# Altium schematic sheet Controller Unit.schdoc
size 495 x 282 mm
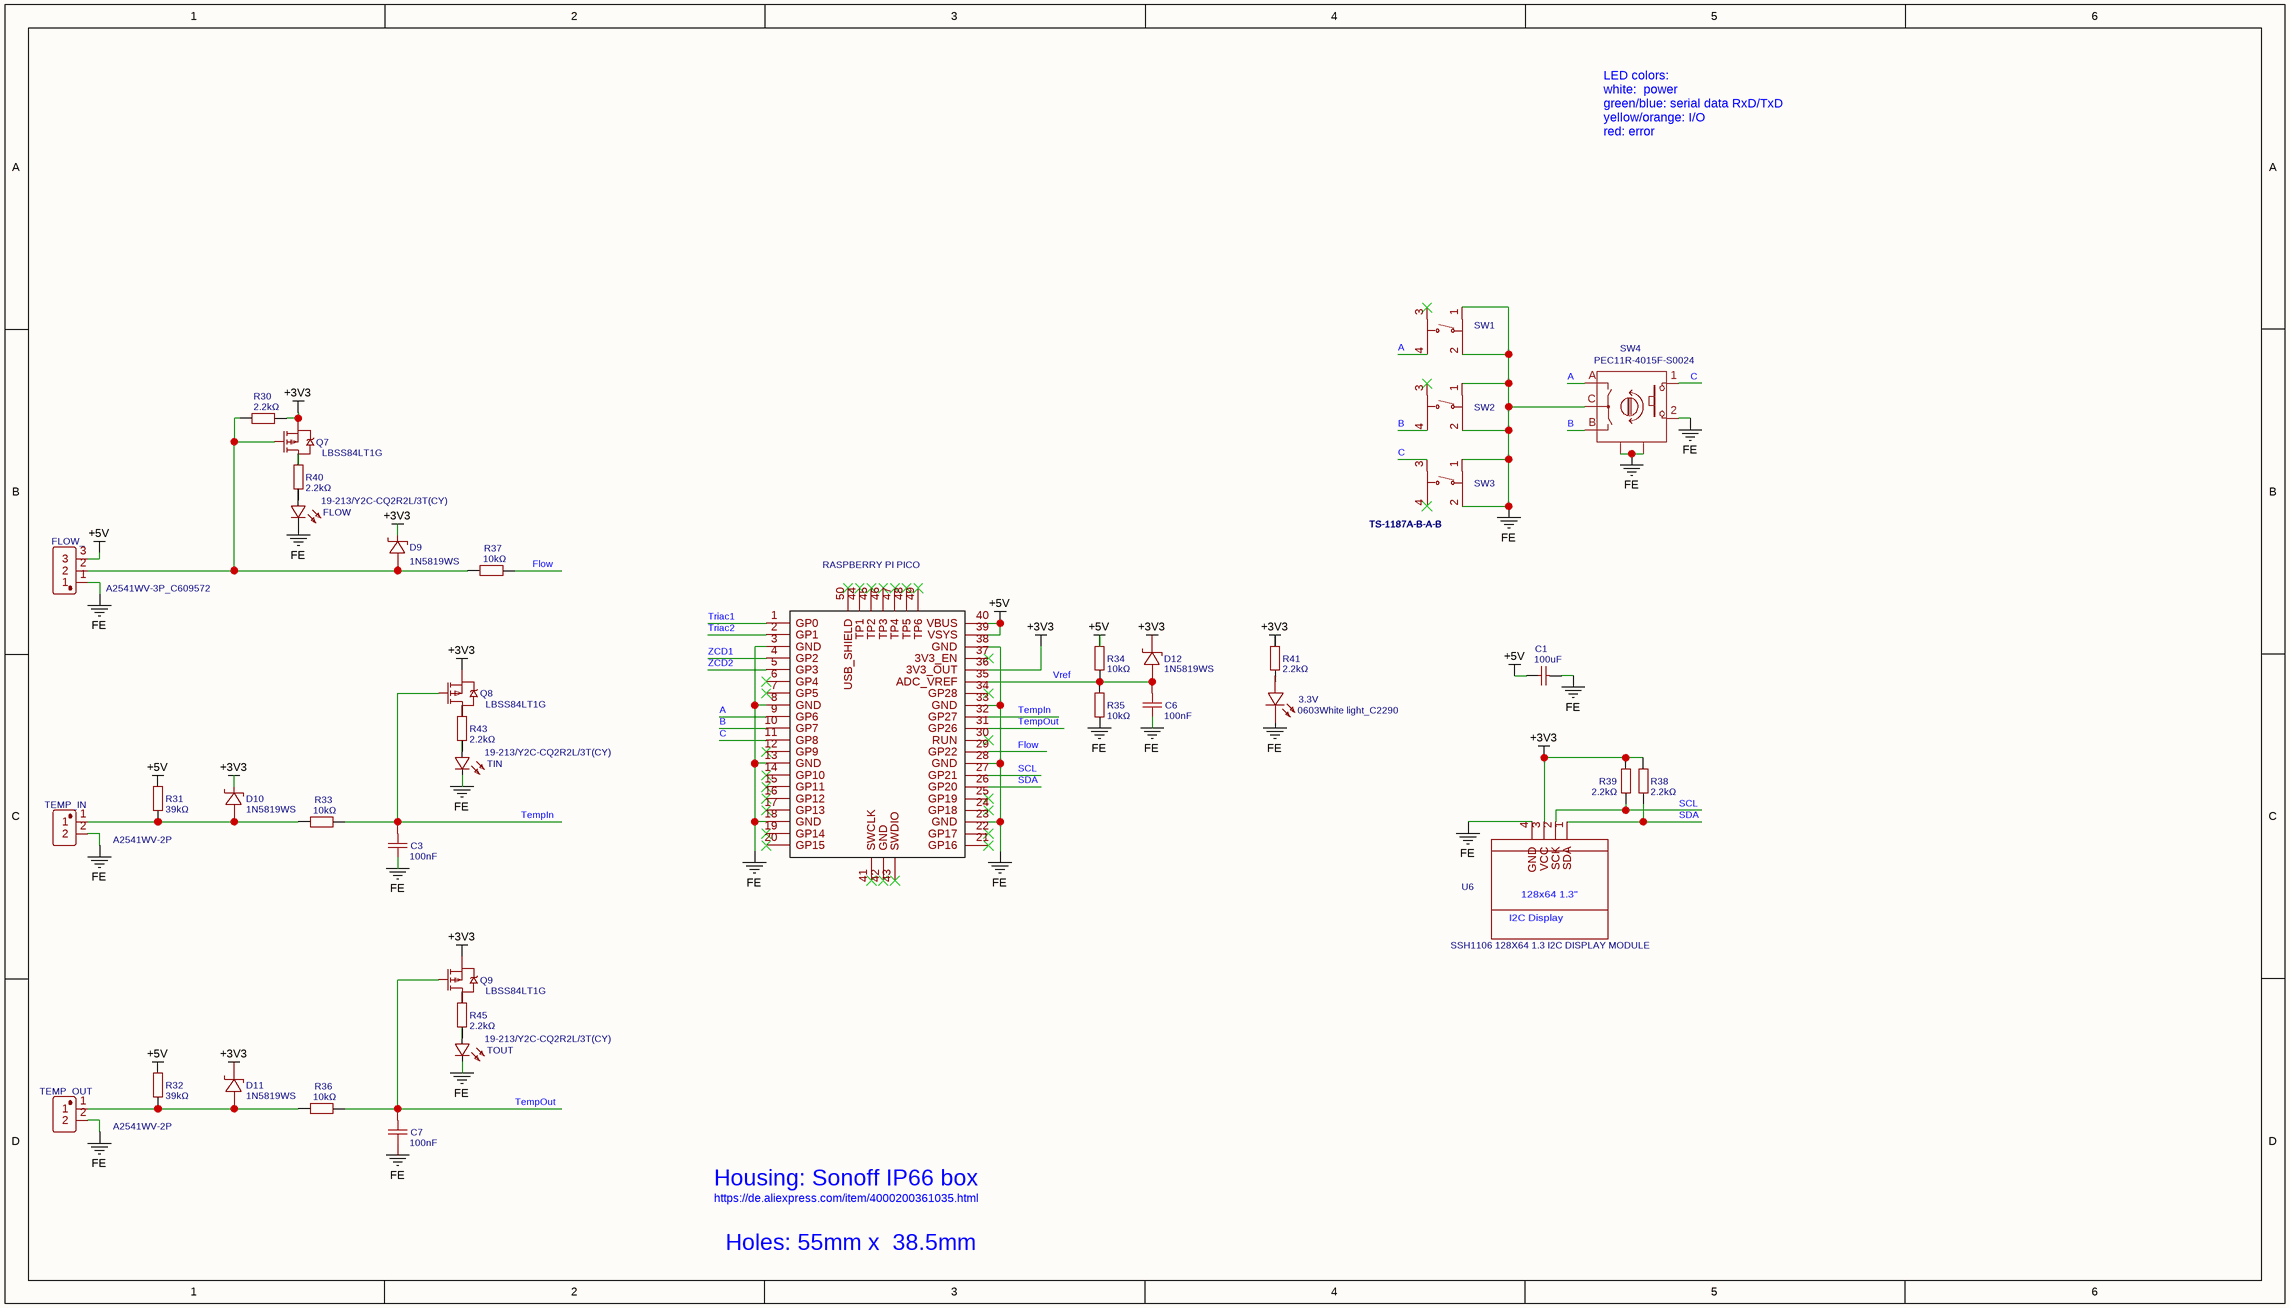
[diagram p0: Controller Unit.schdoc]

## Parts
3.3V  0603White light_C2290  [LED0603-R-RD_WHITE]
C1  100uF  [C1206]
C3  100nF  [C0603]
C6  100nF  [C0603]
C7  100nF  [C0603]
D9  1N5819WS  [SOD-323_L1.8-W1.3-LS2.5-RD]
D10  1N5819WS  [SOD-323_L1.8-W1.3-LS2.5-RD]
D11  1N5819WS  [SOD-323_L1.8-W1.3-LS2.5-RD]
D12  1N5819WS  [SOD-323_L1.8-W1.3-LS2.5-RD]
FLOW  19-213/Y2C-CQ2R2L/3T(CY)  [LED0603-R-RD]
FLOW_  A2541WV-3P_C609572  [HDR-TH_3P-P2.54-V-M]
GP1  RASPBERRY PI PICO  [RASPBERRY PI PICO]
Q7  LBSS84LT1G  [SOT-23_L2.9-W1.3-P1.90-LS2.4-BR]
Q8  LBSS84LT1G  [SOT-23_L2.9-W1.3-P1.90-LS2.4-BR]
Q9  LBSS84LT1G  [SOT-23_L2.9-W1.3-P1.90-LS2.4-BR]
R30  2.2kΩ  [R0603]
R31  39kΩ  [R0603]
R32  39kΩ  [R0603]
R33  10kΩ  [R0603]
R34  10kΩ  [R0603]
R35  10kΩ  [R0603]
R36  10kΩ  [R0603]
R37  10kΩ  [R0603]
R38  2.2kΩ  [R0603]
R39  2.2kΩ  [R0603]
R40  2.2kΩ  [R0603]
R41  2.2kΩ  [R0603]
R43  2.2kΩ  [R0603]
R45  2.2kΩ  [R0603]
SW1  TS-1187A-B-A-B  [SW-SMD_4P-L5.1-W5.1-P3.70-LS6.5-TL-2]
SW2  TS-1187A-B-A-B  [SW-SMD_4P-L5.1-W5.1-P3.70-LS6.5-TL-2]
SW3  TS-1187A-B-A-B  [SW-SMD_4P-L5.1-W5.1-P3.70-LS6.5-TL-2]
SW4  PEC11R-4015F-S0024  [SW-TH_PEC11R-4XXXF-SXXXX]
TEMP_IN  A2541WV-2P  [HDR-TH_P2.54-H-M_A2541WV-2P]
TEMP_OUT  A2541WV-2P  [HDR-TH_P2.54-H-M_A2541WV-2P]
TIN  19-213/Y2C-CQ2R2L/3T(CY)  [LED0603-R-RD]
TOUT  19-213/Y2C-CQ2R2L/3T(CY)  [LED0603-R-RD]
U6  SSH1106 128X64 1.3 I2C DISPLAY MODULE  [SSH1106 128X64 1.3 I2C OLED DISPLAY MODULE]

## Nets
+3V3: D9.1(C) D10.1(C) D11.1(C) D12.1(C) GP1.36(3V3_OUT) Q7.2(S) Q8.2(S) Q9.2(S) R30.1 R38.2 R39.2 R41.2 U6.3(VCC)
+5V: C1.2 FLOW_.3 GP1.39(VSYS) GP1.40(VBUS) R31.2 R32.1 R34.2
FE: 3.3V.2(K) C1.1 C3.1 C6.1 C7.1 FLOW.2(C) FLOW_.1 GP1.3(GND) GP1.8(GND) GP1.13(GND) GP1.18(GND) GP1.23(GND) GP1.28(GND) GP1.33(GND) GP1.38(GND) R35.1 SW1.1(A) SW1.2(B) SW2.1(A) SW2.2(B) SW3.1(A) SW3.2(B) SW4.2 SW4.C SW4.MT1 SW4.MT2 TEMP_IN.2 TEMP_OUT.2 TIN.2(C) TOUT.2(C) U6.4(GND)
A: GP1.9(GP6) SW1.4(D) SW4.A
B: GP1.10(GP7) SW2.4(D) SW4.B
C: GP1.11(GP8) SW3.3(C) SW4.1
Flow: GP1.29(GP22) R37.2
SCL: GP1.27(GP21) R39.1 U6.2(SCK)
SDA: GP1.26(GP20) R38.1 U6.1(SDA)
TempIn: C3.2 GP1.32(GP27) Q8.1(G) R33.2
TempOut: C7.2 GP1.31(GP26) Q9.1(G) R36.2
Triac1: GP1.1(GP0)
Triac2: GP1.2(GP1)
Vref: C6.2 D12.2(A) GP1.35(ADC_VREF) R34.1 R35.2
ZCD1: GP1.4(GP2)
ZCD2: GP1.5(GP3)
Net3.3V_1: 3.3V.1(A) R41.1
NetD9_2: D9.2(A) FLOW_.2 Q7.1(G) R30.2 R37.1
NetD10_2: D10.2(A) R31.1 R33.1 TEMP_IN.1
NetD11_2: D11.2(A) R32.2 R36.1 TEMP_OUT.1
NetFLOW_1: FLOW.1(A) R40.1
NetQ7_3: Q7.3(D) R40.2
NetQ8_3: Q8.3(D) R43.2
NetQ9_3: Q9.3(D) R45.2
NetR43_1: R43.1 TIN.1(A)
NetR45_1: R45.1 TOUT.1(A)

Not connected (* = marked no-connect by the designer): GP1 6(GP4)* 7(GP5)* 12(GP9)* 14(GP10)* 15(GP11)* 16(GP12)* 17(GP13)* 19(GP14)* 20(GP15)* 21(GP16)* 22(GP17)* 24(GP18)* 25(GP19)* 30(RUN)* 34(GP28)* 37(3V3_EN)* 41(SWCLK)* 42(GND)* 43(SWDIO)* 44(TP1)* 45(TP2)* 46(TP3)* 47(TP4)* 48(TP5)* 49(TP6)* 50(USB_SHIELD)*; SW1 3(C)*; SW2 3(C)*; SW3 4(D)*

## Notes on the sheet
- LED colors:
  white:  power
  green/blue: serial data RxD/TxD
  yellow/orange: I/O
  red: error
- https://de.aliexpress.com/item/4000200361035.html
- Housing: Sonoff IP66 box
- Holes: 55mm x  38.5mm

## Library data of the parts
3.3V = 0603White light_C2290: BOM_Manufacturer: KENTO
C1 = 100uF: BOM_Manufacturer Part: CL31A107MQHNNNE; BOM_Manufacturer: SAMSUNG; nameAlias: Capacitance
C3 C6 C7 = 100nF: BOM_Manufacturer: YAGEO; BOM_Manufacturer Part: CC0603KRX7R9BB104; nameAlias: Capacitance
D9-D12 = 1N5819WS: BOM_Manufacturer: Guangdong Hottech; Contributor: LCSC
FLOW TIN TOUT = 19-213/Y2C-CQ2R2L/3T(CY): BOM_Manufacturer: EVERLIGHT
FLOW_ = A2541WV-3P_C609572: BOM_Manufacturer: CJT(Changjiang Connectors); Contributor: LCSC
GP1 = RASPBERRY PI PICO: BOM_Manufacturer: Raspberry Pi Foundation; BOM_Manufacturer Part: RPi Pico; Contributor: PolishFuze
Q7-Q9 = LBSS84LT1G: BOM_Manufacturer: LRC
R30 R38-R41 R43 R45 = 2.2kΩ: BOM_Manufacturer: UniOhm; BOM_Manufacturer Part: 0603WAF2201T5E; nameAlias: Resistance; Resistance (Ohms): 2.2K
R31 R32 = 39kΩ: BOM_Manufacturer: UniOhm; BOM_Manufacturer Part: 0603WAF3902T5E; nameAlias: Resistance; Resistance (Ohms): 39K
R33-R37 = 10kΩ: BOM_Manufacturer: UniOhm; BOM_Manufacturer Part: 0603WAF1002T5E; nameAlias: Resistance; Resistance (Ohms): 10K
SW1-SW3 = TS-1187A-B-A-B: BOM_Manufacturer: XKB Enterprise; Contributor: LCSC
SW4 = PEC11R-4015F-S0024: BOM_Manufacturer: BOURNS; Contributor: LCSC
TEMP_IN TEMP_OUT = A2541WV-2P: BOM_Manufacturer: CJT(Changjiang Connectors); Contributor: LCSC; SMT Type: Extend
U6 = SSH1106 128X64 1.3 I2C DISPLAY MODULE: Contributor: bryan_6020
